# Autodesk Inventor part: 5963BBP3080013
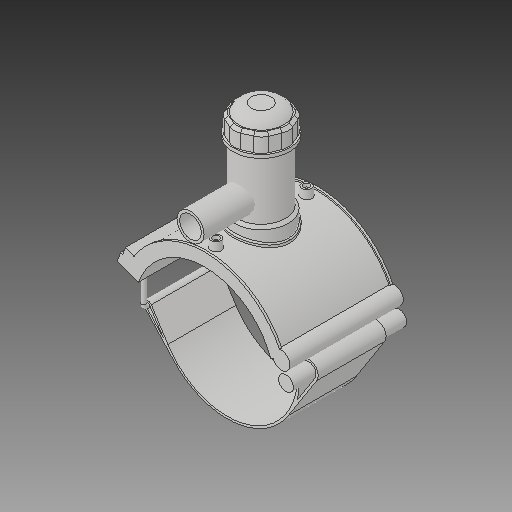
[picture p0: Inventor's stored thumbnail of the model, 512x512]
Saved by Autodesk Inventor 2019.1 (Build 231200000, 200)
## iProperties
Created: 2017-07
Part Number: 5963BBP3080013
Material: Generic
Description: PLASSON TAPPING SADDLE 8''IPS x 1 1/4''IPS
Document SubType Name: Modeling
Designer: KIM
Density: 1 g/cm^3
Appearance: Default
Author: KIM
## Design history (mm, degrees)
derived "5963BBP_5963BUP.ipt"
feature "Solid1::5963BBP_5963BUP.ipt"
feature "Solid2::5963BBP_5963BUP.ipt"
feature "Solid3::5963BBP_5963BUP.ipt"
tag "TaggingFeature1"
body "Solid1"
body "Solid2"
body "Solid3"
other parameters: "d0" = 218.7, "d2" = 269.748, "d3" = 54.675, "d4" = 176.022, "d5" = 0, "d6" = 0.1, "d8" = 0, "d19" = 6, "d20" = 6, "d21" = 105.6132, "d23" = 0, "d24" = 52.8066, "d26" = 0, "d27" = 3, "d28" = 3, "d29" = 3, "d30" = 72.9, "d31" = 6, "d32" = 0, "d33" = 0, "d34" = 0.6, "d40" = 131.91984, "d41" = 87.48, "d43" = 0, "d45" = 0, "d47" = 232.4592, "d70" = 15, "d72" = 0, "d73" = 6, "d75" = 5, "d76" = 0, "d77" = 10.935, "d78" = 139.35, "d79" = 15, "d80" = 70.4088, "d82" = 5 deg, "d84" = 4, "d85" = 14, "d86" = 0, "d87" = 3, "d88" = 0, "d89" = 1, "d90" = 1, "d91" = 140.8176, "d92" = 0, "d93" = 0.5, "d94" = 115.10526, "d96" = 258.76584, "d97" = 3.52044, "d98" = 0, "d102" = 2.187, "d120" = 140 deg, "d121" = 24.228, "d122" = 20 deg, "d123" = 507.384, "d124" = 152.2152, "d126" = 0, "d143" = 225.261, "d145" = 26.91692, "d149" = 3.2805, "d150" = 29.60862, "d153" = 176.022, "d154" = 0, "d156" = 126.846, "d157" = 160 deg, "d159" = 6.9984, "d161" = 3.2805, "d162" = 105.6132, "d163" = 0, "d164" = 109.35, "d167" = 21.87, "d168" = 123.7522, "d170" = 3.2805, "d172" = 0, "d173" = 1, "d175" = 109.35, "d176" = 20 deg, "d177" = 15.309, "d178" = 34.992, "d180" = 0, "d183" = 13.9968, "d184" = 12.2472, "d185" = 57.20715, "d186" = 57.20715, "d187" = 126.846, "d188" = 10.4976, "d189" = 15.309, "d190" = 0, "d191" = 190.269, "d193" = 6.9984, "d194" = 6.16077, "d195" = 90 deg, "d197" = 0, "d199" = 0, "d200" = 17.496, "d202" = 0, "d203" = 177.038, "d204" = 83.106, "d205" = 61.236, "d206" = 74.358, "d207" = 132.7785, "d208" = 138.08964, "d209" = 164.64534, "d210" = 75.2328, "d211" = 87.48, "d212" = 69.984, "d213" = 39.5766, "d216" = 0, "d217" = 21.87, "d218" = 21.87, "d219" = 4.374, "d222" = 218.7, "d224" = 0, "d225" = 65.024, "d226" = 42.1, "d227" = 33.68, "d228" = 109.982, "d230" = 4.374, "d_" = 218.7, "B_" = 179.832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
